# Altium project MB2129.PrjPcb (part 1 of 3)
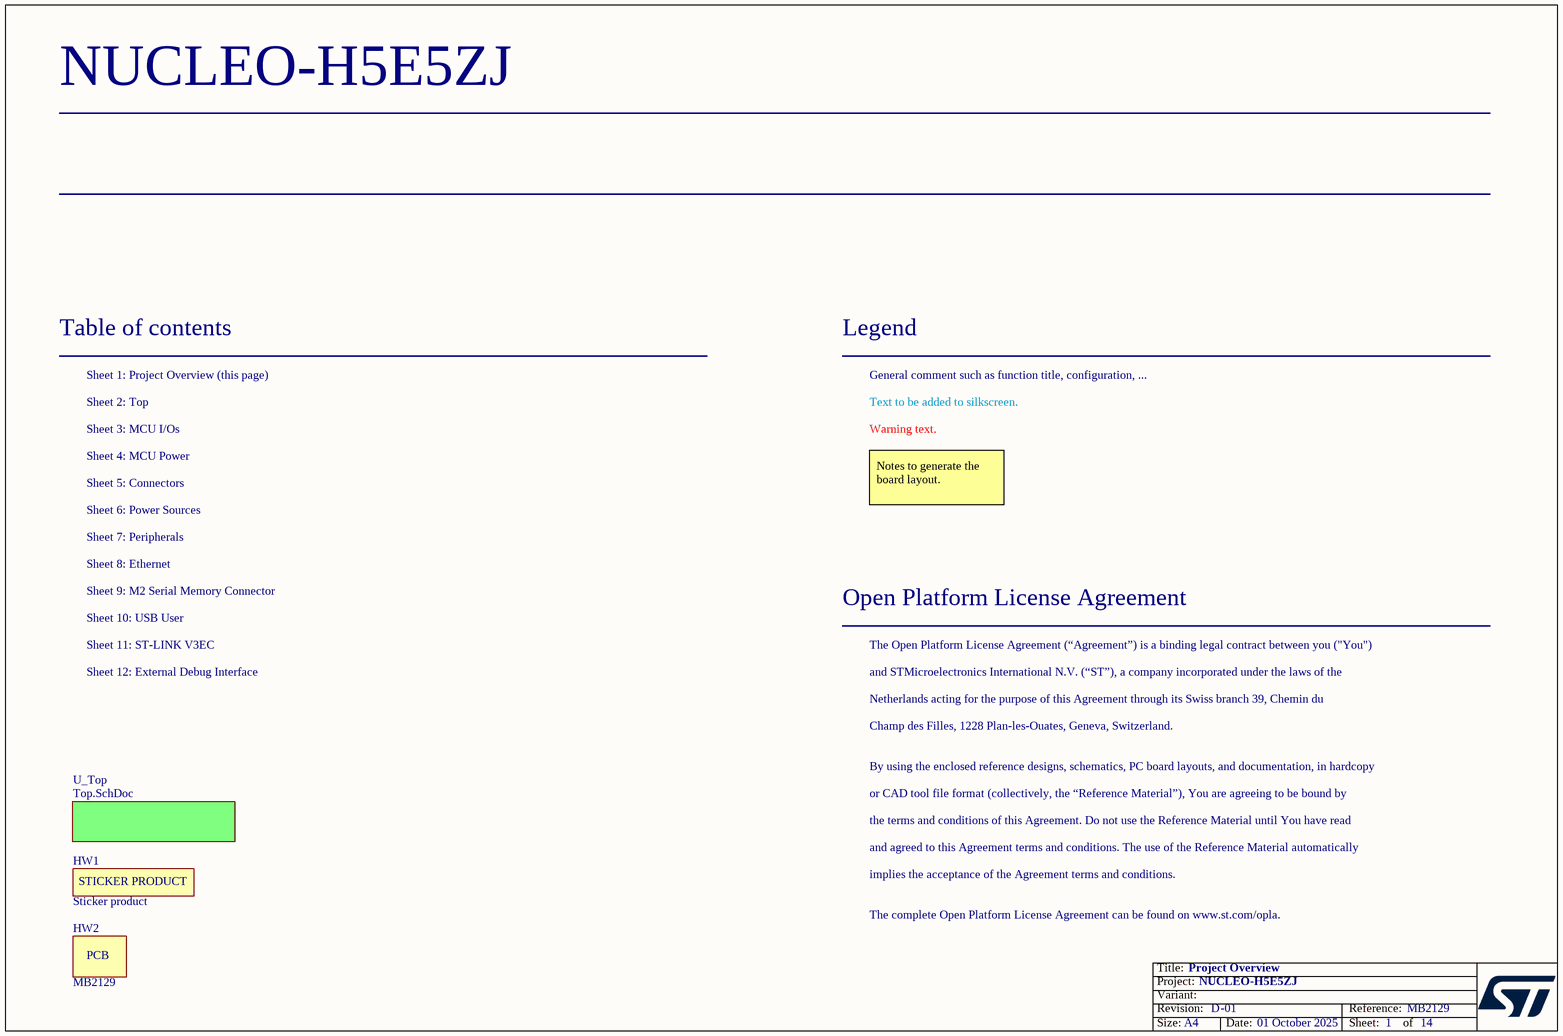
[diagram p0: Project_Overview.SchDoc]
Board_Assembly_Revision: 01; Board_Document_Date: 01 October 2025; Board_Name: NUCLEO-H5E5ZJ; Board_PCB_Revision: D; Board_Reference: MB2129
12 sheets, 381 parts. Net scope: flat (ports and power ports of the same name join across sheets).
Board file: MB2129.PcbDoc
Sheets:
  Project_Overview.SchDoc
    U_Top = Top.SchDoc
      U_Ethernet = Ethernet.SchDoc
      U_STLINK_V3EC = STLINK_V3EC.SchDoc
      U_External_Debug_Interface = External_Debug_Interface.SchDoc
      U_Connectors = Connectors.SchDoc
      U_MCU_Power = MCU_Power.SchDoc
      U_MCU_IOs = MCU_IOs.SchDoc
      U_Power_Sources = Power_Sources.SchDoc
      U_Peripherals = Peripherals.SchDoc
      U_M2_SerMem_Connector = M2_SerMem_Connector.SchDoc
      U_USB_User_UC2.1 = USB_User_UC2.1.SchDoc

## Sheet Project_Overview.SchDoc: Project Overview
size A4; Date: Not used; ApprovedBy: Not used; CheckedBy: Not used; Author: Not used; CompanyName: STMicroelectronics; DrawnBy: Not used; Engineer: Not used; Organization: Not used; Address1: Not used; Address2: Not used; Address3: Not used; Address4: Not used; DocumentNumber: 1; Revision: Not used; SheetNumber: 1; SheetTotal: 14

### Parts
HW1  value Sticker product  [STICKER_PRODUCT_25X9]  (hidden comment: STICKER_PRODUCT)  (no BOM)
HW2  value MB2129  (hidden comment: PCB)  (mechanical)

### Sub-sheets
U_Top = Top.SchDoc: no entries

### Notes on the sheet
- Table of contents
- Sheet 1: Project Overview (this page)
- Legend
- General comment such as function title, configuration, ...
- Sheet 2: Top
- Sheet 3: MCU I/Os
- Text to be added to silkscreen.
- Warning text.
- Sheet 4: MCU Power
- Sheet 5: Connectors
- Sheet 6: Power Sources
- Notes to generate the board layout.
- Sheet 8: Ethernet
- Sheet 7: Peripherals
- Sheet 10: USB User
- Sheet 11: ST-LINK V3EC
- Sheet 9: M2 Serial Memory Connector
- Open Platform License Agreement
- The Open Platform License Agreement (“Agreement”) is a binding legal contract between you ("You")
- Sheet 12: External Debug Interface
- and STMicroelectronics International N.V. (“ST”), a company incorporated under the laws of the
- Netherlands acting for the purpose of this Agreement through its Swiss branch 39, Chemin du
- Champ des Filles, 1228 Plan-les-Ouates, Geneva, Switzerland.
- By using the enclosed reference designs, schematics, PC board layouts, and documentation, in hardcopy
- or CAD tool file format (collectively, the “Reference Material”), You are agreeing to be bound by
- the terms and conditions of this Agreement. Do not use the Reference Material until You have read
- and agreed to this Agreement terms and conditions. The use of the Reference Material automatically
- implies the acceptance of the Agreement terms and conditions.
- The complete Open Platform License Agreement can be found on www.st.com/opla.

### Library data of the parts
HW1 = MCD-00547: Sticker product 25x9 mm; Part_Type: Misc; Part_Preference: Recommended; ShowFields: YES; ID: 3197
HW2 = MCD-04587: MB2129_RevB, 6L2S, STM32H5E5; Part_Preference: Recommended; Manufacturer: EISUN ELECTRONICS SHENZHEN CO; ShowFields: YES; ID: 6703

## Sheet Top.SchDoc: Top
size A4; Date: Not used; ApprovedBy: Not used; CheckedBy: Not used; Author: Not used; CompanyName: STMicroelectronics; DrawnBy: Not used; Engineer: Not used; Organization: Not used; Address1: Not used; Address2: Not used; Address3: Not used; Address4: Not used; DocumentNumber: 2; Revision: Not used; SheetNumber: 2; SheetTotal: 14
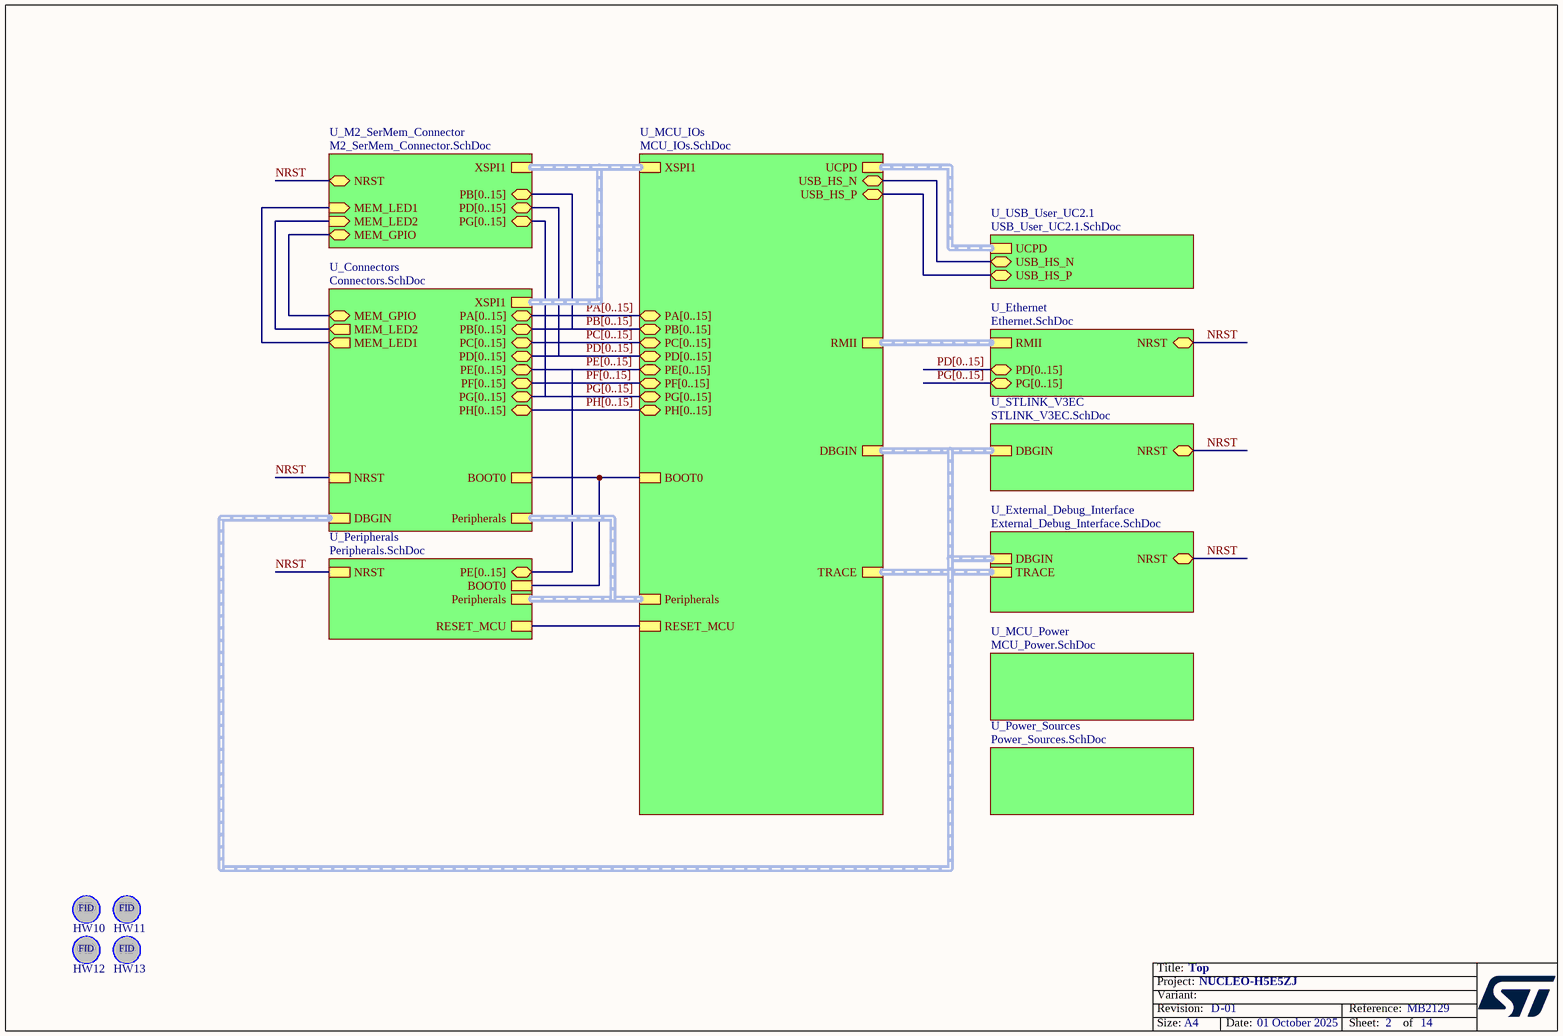
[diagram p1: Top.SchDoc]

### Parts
HW10  FiducialPad  [MIRE_PLACE_SMD_0P8MM]  (value not drawn)  (no BOM)
HW11  FiducialPad  [MIRE_PLACE_SMD_0P8MM]  (value not drawn)  (no BOM)
HW12  FiducialPad  [MIRE_PLACE_SMD_0P8MM]  (value not drawn)  (no BOM)
HW13  FiducialPad  [MIRE_PLACE_SMD_0P8MM]  (value not drawn)  (no BOM)

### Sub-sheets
U_Connectors = Connectors.SchDoc: PC[0..15] (bidir), PE[0..15] (bidir), PF[0..15] (bidir), PG[0..15] (bidir), PA[0..15] (bidir), PB[0..15] (bidir), BOOT0, PD[0..15] (bidir), NRST, Peripherals (harness Peripherals), MEM_LED1 (out), MEM_LED2 (out), MEM_GPIO (bidir), PH[0..15] (bidir), XSPI1 (harness XSPI1), DBGIN (harness DBGIN)
U_Ethernet = Ethernet.SchDoc: RMII (harness RMII), NRST (bidir), PD[0..15] (bidir), PG[0..15] (bidir)
U_External_Debug_Interface = External_Debug_Interface.SchDoc: TRACE (harness TRACE), NRST (bidir), DBGIN (harness DBGIN)
U_M2_SerMem_Connector = M2_SerMem_Connector.SchDoc: PB[0..15] (bidir), XSPI1 (harness XSPI1), NRST (bidir), MEM_LED1 (in), MEM_LED2 (in), MEM_GPIO (bidir), PD[0..15] (bidir), PG[0..15] (bidir)
U_MCU_IOs = MCU_IOs.SchDoc: Peripherals (harness Peripherals), TRACE (harness TRACE), RMII (harness RMII), PD[0..15] (bidir), PE[0..15] (bidir), PG[0..15] (bidir), PC[0..15] (bidir), PA[0..15] (bidir), PF[0..15] (bidir), PB[0..15] (bidir), BOOT0, UCPD (harness UCPD), USB_HS_N (bidir), USB_HS_P (bidir), DBGIN (harness DBGIN), XSPI1 (harness XSPI1), RESET_MCU, PH[0..15] (bidir)
U_MCU_Power = MCU_Power.SchDoc: no entries
U_Peripherals = Peripherals.SchDoc: Peripherals (harness Peripherals), NRST, BOOT0, RESET_MCU, PE[0..15] (bidir)
U_Power_Sources = Power_Sources.SchDoc: no entries
U_STLINK_V3EC = STLINK_V3EC.SchDoc: NRST (bidir), DBGIN (harness DBGIN)
U_USB_User_UC2.1 = USB_User_UC2.1.SchDoc: USB_HS_N (bidir), USB_HS_P (bidir), UCPD (harness UCPD)

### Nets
NRST: sheet U_Ethernet/NRST, sheet U_STLINK_V3EC/NRST, sheet U_External_Debug_Interface/NRST, sheet U_Connectors/NRST, sheet U_Peripherals/NRST, sheet U_M2_SerMem_Connector/NRST
(unnamed): sheet U_Connectors/BOOT0, sheet U_MCU_IOs/BOOT0, sheet U_Peripherals/BOOT0
(unnamed): sheet U_Connectors/MEM_LED1, sheet U_M2_SerMem_Connector/MEM_LED1  [a separate net that carries the same name]
(unnamed): sheet U_Connectors/MEM_LED2, sheet U_M2_SerMem_Connector/MEM_LED2  [a separate net that carries the same name]
(unnamed): sheet U_Connectors/MEM_GPIO, sheet U_M2_SerMem_Connector/MEM_GPIO  [a separate net that carries the same name]
(unnamed): sheet U_MCU_IOs/USB_HS_N, sheet U_USB_User_UC2.1/USB_HS_N  [a separate net that carries the same name]
(unnamed): sheet U_MCU_IOs/USB_HS_P, sheet U_USB_User_UC2.1/USB_HS_P  [a separate net that carries the same name]
(unnamed): sheet U_MCU_IOs/RESET_MCU, sheet U_Peripherals/RESET_MCU  [a separate net that carries the same name]

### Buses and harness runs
bus PA[0..15] = sheet U_Connectors/PA[0..15] = sheet U_MCU_IOs/PA[0..15]
bus PB[0..15] = sheet U_Connectors/PB[0..15] = sheet U_M2_SerMem_Connector/PB[0..15] = sheet U_MCU_IOs/PB[0..15]
bus PC[0..15] = sheet U_Connectors/PC[0..15] = sheet U_MCU_IOs/PC[0..15]
bus PD[0..15] = sheet U_Connectors/PD[0..15] = sheet U_M2_SerMem_Connector/PD[0..15] = sheet U_MCU_IOs/PD[0..15]
bus PD[0..15] = sheet U_Ethernet/PD[0..15]
bus PE[0..15] = sheet U_Connectors/PE[0..15] = sheet U_MCU_IOs/PE[0..15] = sheet U_Peripherals/PE[0..15]
bus PF[0..15] = sheet U_Connectors/PF[0..15] = sheet U_MCU_IOs/PF[0..15]
bus PG[0..15] = sheet U_Connectors/PG[0..15] = sheet U_M2_SerMem_Connector/PG[0..15] = sheet U_MCU_IOs/PG[0..15]
bus PG[0..15] = sheet U_Ethernet/PG[0..15]
bus PH[0..15] = sheet U_Connectors/PH[0..15] = sheet U_MCU_IOs/PH[0..15]
harness sheet U_Connectors/DBGIN = sheet U_External_Debug_Interface/DBGIN = sheet U_MCU_IOs/DBGIN = sheet U_STLINK_V3EC/DBGIN
harness sheet U_Connectors/Peripherals = sheet U_MCU_IOs/Peripherals = sheet U_Peripherals/Peripherals
harness sheet U_Connectors/XSPI1 = sheet U_M2_SerMem_Connector/XSPI1 = sheet U_MCU_IOs/XSPI1
harness sheet U_Ethernet/RMII = sheet U_MCU_IOs/RMII
harness sheet U_External_Debug_Interface/TRACE = sheet U_MCU_IOs/TRACE
harness sheet U_MCU_IOs/UCPD = sheet U_USB_User_UC2.1/UCPD

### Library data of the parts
HW10-HW13 = MCD-03135: Fiducial Pad, 0.8mm; Part_Type: Misc; Part_Preference: Recommended; ShowFields: YES; ID: 5251; Component_Country_Of_Origin: Unknown

## Sheet Ethernet.SchDoc: Ethernet
size A4; Date: Not used; ApprovedBy: Not used; CheckedBy: Not used; Author: Not used; CompanyName: STMicroelectronics; DrawnBy: Not used; Engineer: Not used; Organization: Not used; Address1: Not used; Address2: Not used; Address3: Not used; Address4: Not used; DocumentNumber: 8; Revision: Not used; SheetNumber: 8; SheetTotal: 14
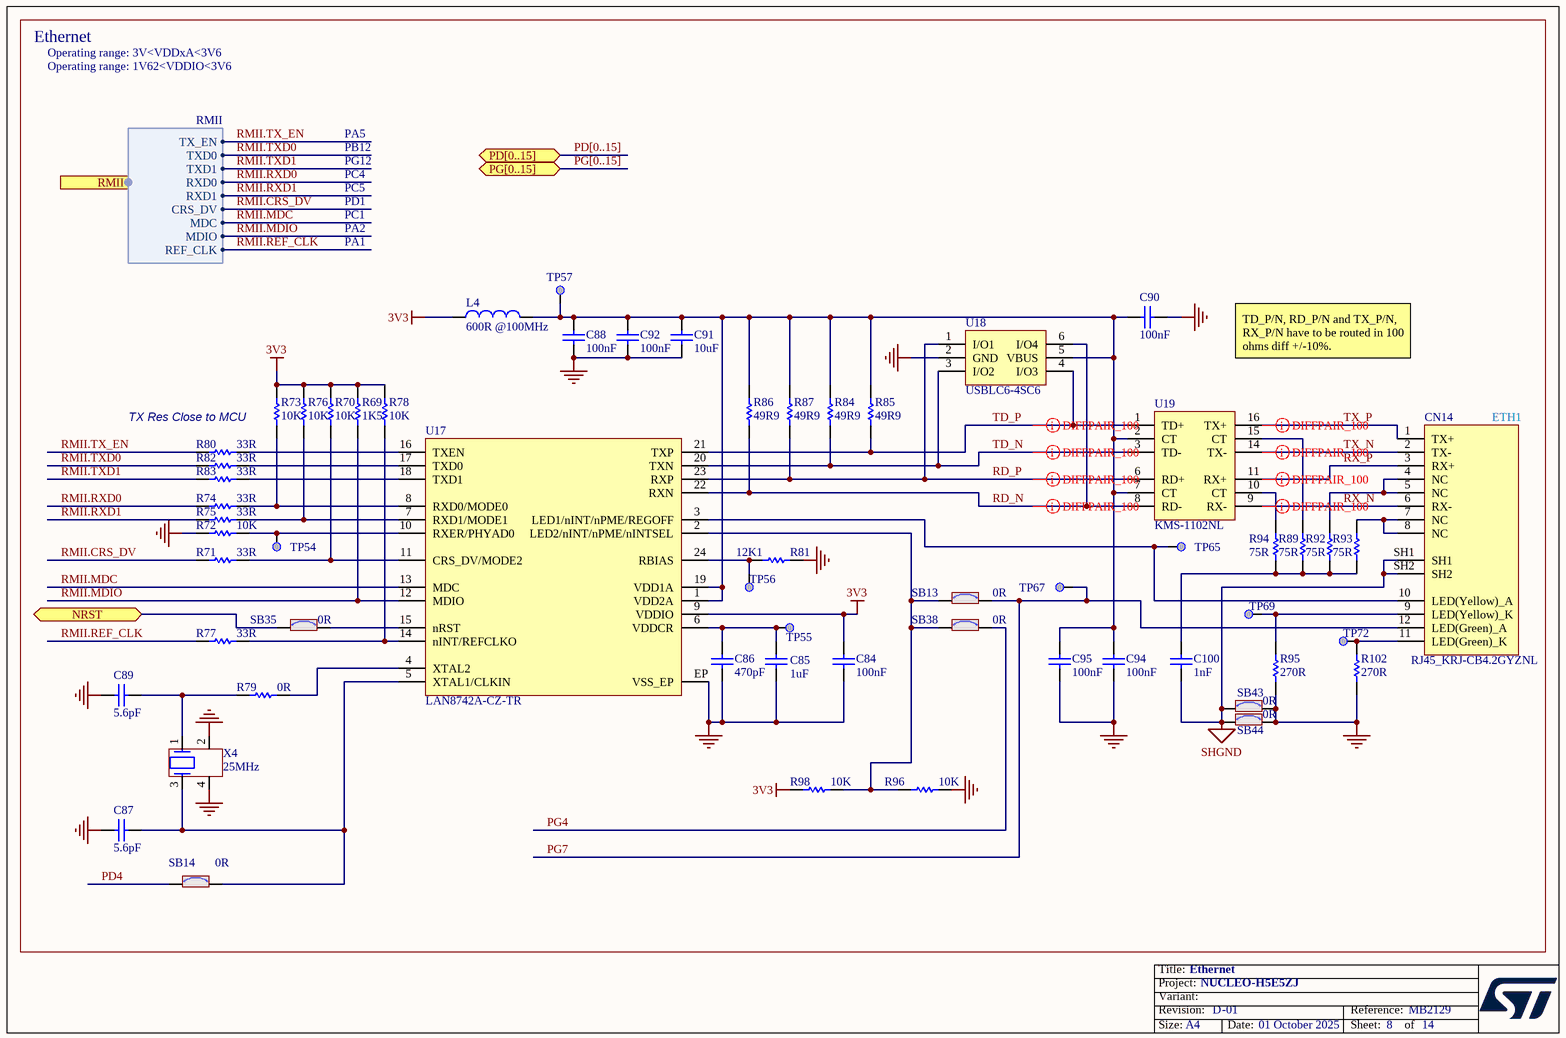
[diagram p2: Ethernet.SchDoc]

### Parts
C84  value 100nF  [C0402]  (hidden comment: Capacitor)
C85  value 1uF  [C0402]  (hidden comment: Capacitor)
C86  value 470pF  [C0402]  (hidden comment: Capacitor)
C87  value 5.6pF  [C0402]  (hidden comment: Capacitor)
C88  value 100nF  [C0402]  (hidden comment: Capacitor)
C89  value 5.6pF  [C0402]  (hidden comment: Capacitor)
C90  value 100nF  [C0402]  (hidden comment: Capacitor)
C91  value 10uF  [C0603]  (hidden comment: Capacitor)
C92  value 100nF  [C0402]  (hidden comment: Capacitor)
C94  value 100nF  [C0402]  (hidden comment: Capacitor)
C95  value 100nF  [C0402]  (hidden comment: Capacitor)
C100  value 1nF  [C1206_H1P6]  (hidden comment: Capacitor)
CN14  RJ45_KRJ-CB4.2GYZNL  [CON_RJ45_DGKYD_KRJ-CB4.2GYZNL]
L4  value 600R @100MHz  [L0603]  (hidden comment: BEAD)
R69  value 1K5  [R0402]  (hidden comment: Resistor)
R70  value 10K  [R0402]  (hidden comment: Resistor)
R71  value 33R  [R0402]  (hidden comment: Resistor)
R72  value 10K  [R0402]  (hidden comment: Resistor)
R73  value 10K  [R0402]  (hidden comment: Resistor)
R74  value 33R  [R0402]  (hidden comment: Resistor)
R75  value 33R  [R0402]  (hidden comment: Resistor)
R76  value 10K  [R0402]  (hidden comment: Resistor)
R77  value 33R  [R0402]  (hidden comment: Resistor)
R78  value 10K  [R0402]  (hidden comment: Resistor)
R79  value 0R  [R0402]  (hidden comment: Resistor)
R80  value 33R  [R0402]  (hidden comment: Resistor)
R81  value 12K1  [R0402]  (hidden comment: Resistor)
R82  value 33R  [R0402]  (hidden comment: Resistor)
R83  value 33R  [R0402]  (hidden comment: Resistor)
R84  value 49R9  [R0402]  (hidden comment: Resistor)
R85  value 49R9  [R0402]  (hidden comment: Resistor)
R86  value 49R9  [R0402]  (hidden comment: Resistor)
R87  value 49R9  [R0402]  (hidden comment: Resistor)
R89  value 75R  [R0402]  (hidden comment: Resistor)
R92  value 75R  [R0402]  (hidden comment: Resistor)
R93  value 75R  [R0402]  (hidden comment: Resistor)
R94  value 75R  [R0402]  (hidden comment: Resistor)
R95  value 270R  [R0402]  (hidden comment: Resistor)
R96  value 10K  [R0402]  (hidden comment: Resistor)
R98  value 10K  [R0402]  (hidden comment: Resistor)
R102  value 270R  [R0402]  (hidden comment: Resistor)
SB13  value 0R  [SOLDER-BRIDGE_R0603-0R]  (hidden comment: SB_ON)
SB14  value 0R  [SOLDER-BRIDGE_R0402-0R]  (hidden comment: SB_ON)
SB35  value 0R  [SOLDER-BRIDGE_R0603-0R]  (hidden comment: SB_ON)
SB38  value 0R  [SOLDER-BRIDGE_R0603-0R]  (hidden comment: SB_ON)
SB43  value 0R  [SOLDER-BRIDGE_R0603-0R]  (hidden comment: SB_ON)
SB44  value 0R  [SOLDER-BRIDGE_R0603-0R]  (hidden comment: SB_ON)
TP54  Test Point  [TP_SMD_0-6MM]  (value not drawn)  (no BOM)
TP55  Test Point  [TP_SMD_0-6MM]  (value not drawn)  (no BOM)
TP56  Test Point  [TP_SMD_0-6MM]  (value not drawn)  (no BOM)
TP57  Test Point  [TP_SMD_0-6MM]  (value not drawn)  (no BOM)
TP65  Test Point  [TP_SMD_0-6MM]  (value not drawn)  (no BOM)
TP67  Test Point  [TP_SMD_0-6MM]  (value not drawn)  (no BOM)
TP69  Test Point  [TP_SMD_0-6MM]  (value not drawn)  (no BOM)
TP72  Test Point  [TP_SMD_0-6MM]  (value not drawn)  (no BOM)
U17  LAN8742A-CZ-TR  [ICC_VQFN24-EPAD_4X4_P050]
U18  USBLC6-4SC6  [ESD_SOT23-6L]
U19  KMS-1102NL  [TRS_DGKYD_KMS-1102NL]
X4  value 25MHz  [CRY_NX2016SA_4P]  (hidden comment: XTAL_4_PINS)

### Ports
NRST (bidir), PD[0..15] (bidir), PG[0..15] (bidir), RMII (harness RMII)

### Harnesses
RMII: TX_EN, TXD0, TXD1, RXD0, RXD1, CRS_DV, MDC, MDIO, REF_CLK

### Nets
3V3: C84.2 L4.1 R69.2 R70.2 R73.2 R76.2 R78.2 R98.2 U17.9(VDDIO)
GND: C84.1 C85.1 C86.1 C87.1 C88.1 C89.1 C90.1 C91.1 C92.1 C94.1 C95.1 R72.2 R81.2 R95.1 R96.1 R102.1 SB43.2 SB44.2 U17.EP(VSS_EP) U18.2(GND) X4.2 X4.4
SHGND: C100.1 CN14.SH1 CN14.SH2 SB43.1 SB44.1
NRST: SB35.1 ; port NRST
PD4: SB14.1
PG4: SB38.2
PG7: CN14.12(LED(Green)_A) SB13.2 TP67.1
RD_N: R86.1 U17.22(RXN) U18.6(I/O4) U19.8(RD-)
RD_P: R87.1 U17.23(RXP) U18.1(I/O1) U19.6(RD+)
RMII.CRS_DV: R71.1 ; port RMII.CRS_DV
RMII.MDC: U17.13(MDC) ; port RMII.MDC
RMII.MDIO: R69.1 U17.12(MDIO) ; port RMII.MDIO
RMII.REF_CLK: R77.1 ; port RMII.REF_CLK
RMII.RXD0: R74.1 ; port RMII.RXD0
RMII.RXD1: R75.1 ; port RMII.RXD1
RMII.TX_EN: R80.1 ; port RMII.TX_EN
RMII.TXD0: R82.1 ; port RMII.TXD0
RMII.TXD1: R83.1 ; port RMII.TXD1
RX_N: CN14.6(RX-) U19.9(RX-)
RX_P: CN14.3(RX+) U19.11(RX+)
TD_N: R84.1 U17.20(TXN) U18.3(I/O2) U19.3(TD-)
TD_P: R85.1 U17.21(TXP) U18.4(I/O3) U19.1(TD+)
TX_N: CN14.2(TX-) U19.14(TX-)
TX_P: CN14.1(TX+) U19.16(TX+)
NetC85_2: C85.2 C86.2 TP55.1 U17.6(VDDCR)
NetC87_2: C87.2 SB14.2 U17.5(XTAL1/CLKIN) X4.3
NetC88_2: C88.2 C90.2 C91.2 C92.2 C94.2 C95.2 L4.2 R84.2 R85.2 R86.2 R87.2 TP57.1 U17.1(VDD2A) U17.19(VDD1A) U18.5(VBUS) U19.2(CT) U19.7(CT)
NetC89_2: C89.2 R79.1 X4.1
NetC100_2: C100.2 R89.1 R92.1 R93.1 R94.1
NetCN14_4: CN14.4(NC) CN14.5(NC) R92.2
NetCN14_7: CN14.7(NC) CN14.8(NC) R93.2
NetCN14_9: CN14.9(LED(Yellow)_K) R95.2 TP69.1
NetCN14_10: CN14.10(LED(Yellow)_A) TP65.1 U17.3(LED1/nINT/nPME/REGOFF)
NetCN14_11: CN14.11(LED(Green)_K) R102.2 TP72.1
NetR70_1: R70.1 R71.2 U17.11(CRS_DV/MODE2)
NetR72_1: R72.1 TP54.1 U17.10(RXER/PHYAD0)
NetR73_1: R73.1 R74.2 U17.8(RXD0/MODE0)
NetR75_2: R75.2 R76.1 U17.7(RXD1/MODE1)
NetR77_2: R77.2 R78.1 U17.14(nINT/REFCLKO)
NetR79_2: R79.2 U17.4(XTAL2)
NetR80_2: R80.2 U17.16(TXEN)
NetR81_1: R81.1 TP56.1 U17.24(RBIAS)
NetR82_2: R82.2 U17.17(TXD0)
NetR83_2: R83.2 U17.18(TXD1)
NetR89_2: R89.2 U19.15(CT)
NetR94_2: R94.2 U19.10(CT)
NetR96_2: R96.2 R98.1 SB13.1 SB38.1 U17.2(LED2/nINT/nPME/nINTSEL)
NetSB35_2: SB35.2 U17.15(nRST)

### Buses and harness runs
bus PD[0..15] = port PD[0..15]
bus PG[0..15] = port PG[0..15]

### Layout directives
differential pair; differential pair class DiffPair_100; net class 100 ohms diff: RD_N, RD_P, RX_N, RX_P, TD_N, TD_P, TX_N, TX_P

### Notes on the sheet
- Operating range: 3V<VDDxA<3V6
- Operating range: 1V62<VDDIO<3V6
- PA5
- PB12
- PG12
- PC4
- PC5
- PD1
- PC1
- PA2
- PA1
- TD_P/N, RD_P/N and TX_P/N, RX_P/N have to be routed in 100 ohms diff +/-10%.
- TX Res Close to MCU
- (near CN14) ETH1

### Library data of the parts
C84 C88 C90 C92 C94 C95 = MCD-00006: Capacitor, MLCC, 100nF, 16V, X7R, +/-10%, 0402, T=0.5mm; Part_Preference: Recommended; Manufacturer: YAGEO; Manufacturer_Part_Number: CC0402KRX7R7BB104; Partial_Alternate_Internal_Part_Number: MCD-03299; Order_Code_RS: 9402047; Component_Country_Of_Origin: China; ShowFields: YES; ID: 2474
C85 = MCD-01722: Capacitor, MLCC, 1uF, 10V, X5R, +/-10%, 0402, T=0.5mm; Part_Preference: Recommended; Manufacturer: YAGEO; Manufacturer_Part_Number: CC0402KRX5R6BB105; Component_Country_Of_Origin: China; ShowFields: YES; ID: 3822
C86 = MCD-00724: Capacitor, MLCC, 470pF, 50V, NPO, +/-5%, 0402, T=0.5mm; Manufacturer_Part_Number: CC0402JRNPO9BN471; Manufacturer: YAGEO; Part_Preference: Recommended; Order_Code_RS: 199-2186; Component_Country_Of_Origin: China; ShowFields: YES; ID: 3023
C87 C89 = MCD-01374: Capacitor, MLCC, 5.6pF, 50V, NPO, +/-0.1pF, 0402, T=0.5mm; Manufacturer_Part_Number: CC0402BRNPO9BN5R6; Manufacturer: YAGEO; Part_Preference: Recommended; Component_Country_Of_Origin: China; ShowFields: YES; ID: 3474
C91 = MCD-00099: Capacitor, MLCC, 10uF, 10V, X5R, +/-10%, 0603, T=0.8mm; Part_Preference: Recommended; Manufacturer: MURATA; Manufacturer_Part_Number: GRM188R61A106KE69D; Partial_Alternate_Internal_Part_Number: MCD-03152; Order_Code_RS: 2494233; Component_Country_Of_Origin: Japan°°; ShowFields: YES; ID: 2770
C100 = MCD-00722: Capacitor, MLCC, 1nF, 2KV, X7R, +/-10%, 1206, T=1.25mm; Manufacturer_Part_Number: CC1206KKX7RDBB102; Manufacturer: YAGEO; Part_Preference: Recommended; Component_Country_Of_Origin: China; ShowFields: YES; ID: 3027
CN14 = MCD-00717: Connector_RJ45, single port, with LEDS, T= 11.05mm; Manufacturer: DONGGUAN KEYOUDA ELECTRONIC TECHNOLOGY; Part_Preference: Recommended; Component_Country_Of_Origin: Unknown; ShowFields: YES; ID: 3029
L4 = MCD-02437: Ferrite bead, 600R@100MHz, +/-25%, 500mA, 380mR, 0603, T=0.8mm; Part_Type: Inductor; Part_Preference: Recommended; Manufacturer: MURATA; Manufacturer_Part_Number: BLM18AG601SN1D; Order_Code_RS: 724-1299; Component_Country_Of_Origin: Japan°; ShowFields: YES; ID: 4543
R69 = MCD-00068: Resistor, 1K5, 0402, +/-1%, 1/16W; Manufacturer_Part_Number: RC0402FR-071K5L; Manufacturer: YAGEO; Part_Preference: Recommended; Order_Code_RS: 9239251; Component_Country_Of_Origin: China; ShowFields: YES; ID: 2524
R70 R72 R73 R76 R78 R96 R98 = MCD-00053: Resistor, 10K, 0402, +/-1%, 1/16W; Manufacturer_Part_Number: RC0402FR-0710KL; Manufacturer: YAGEO; BMS_Part_Number: 9131590; Part_Preference: Recommended; Order_Code_RS: 9239359; Component_Country_Of_Origin: China; ShowFields: YES; ID: 2539
R71 R74 R75 R77 R80 R82 R83 = MCD-00455: Resistor, 33R, 0402, +/-1%, 1/16W; Manufacturer_Part_Number: RC0402FR-0733RL; Manufacturer: YAGEO; Part_Preference: Recommended; Component_Country_Of_Origin: China; ShowFields: YES; ID: 2821
R79 = MCD-00052: Resistor, 0R, 0402, +/-5%, 1/16W; Manufacturer_Part_Number: RC0402JR-070RL; Manufacturer: YAGEO; Part_Preference: Recommended; Order_Code_RS: 9232516RL; Component_Country_Of_Origin: China; ShowFields: YES; ID: 2540
R81 = MCD-00723: Resistor, 12K1, 0402, +/-1%, 1/16W; Manufacturer_Part_Number: RC0402FR-0712K1L; Manufacturer: YAGEO; Part_Preference: Recommended; Component_Country_Of_Origin: China; ShowFields: YES; ID: 3022
R84-R87 = MCD-00565: Resistor, 49R9, 0402, +/-1%, 1/16W; Manufacturer_Part_Number: RC0402FR-0749R9L; Manufacturer: YAGEO; Part_Preference: Recommended; Component_Country_Of_Origin: China; ShowFields: YES; ID: 3178
R89 R92-R94 = MCD-00515: Resistor, 75R, 0402, +/-1%, 1/16W; Manufacturer_Part_Number: RC0402FR-0775RL; Manufacturer: YAGEO; Part_Preference: Recommended; Component_Country_Of_Origin: China; ShowFields: YES; ID: 3229
R95 R102 = MCD-00441: Resistor, 270R, 0402, +/-1%, 1/16W; Manufacturer_Part_Number: RC0402FR-07270RL; Manufacturer: YAGEO; Part_Preference: Recommended; Component_Country_Of_Origin: China; ShowFields: YES; ID: 2838
SB13 SB35 SB38 SB43 SB44 = MCD-00071: Resistor, 0R, SB0603, 5%, 0.1W; Manufacturer_Part_Number: RC0603JR-070RL; Manufacturer: YAGEO; Part_Preference: Recommended; Manufacturer_HQ_COO: Unknown; Order_Code_RS: 199-5647; Component_Country_Of_Origin: China; ShowFields: YES; ID: 2521
SB14 = MCD-01618: Resistor, 0R, SB0402, 5%, 0.063W; Manufacturer_Part_Number: RC0402JR-070RL; Manufacturer: YAGEO; Part_Preference: Recommended; Order_Code_RS: 618-5804; Component_Country_Of_Origin: China; ID: 3718; ShowFields: YES
TP54-TP57 TP65 TP67 TP69 TP72 = MCD-00631: Test Point 0.6mm; Part_Type: Misc; Part_Preference: Recommended; ShowFields: YES; ID: 3108; Component_Country_Of_Origin: Unknown
U17 = MCD-00719: ETHERNET Transceiver, Small Footprint RMII, 10/100M, with HP Auto-MDIX and flexPWR technology; BMS_Part_Number: 9177984; Part_Type: IC; Part_Preference: Recommended; Manufacturer: MICROCHIP; Partial_Alternate_Internal_Part_Number: MCD-03200; Order_Code_RS: 215-3925; Component_Country_Of_Origin: Unknown; ShowFields: YES; ID: 3026
U18 = MCD-00250: Very low capacitance ESD protection , 4 lines; Part_Type: IC; Manufacturer: STMICROELECTRONICS; BMS_Part_Number: 9151001; Part_Preference: Recommended; Manufacturer_HQ_COO: EU; Component_Country_Of_Origin: China; ShowFields: YES; ID: 2616
U19 = MCD-00718: Discrete magnetic transformer module, 16 pins, SMT, 100 Base-TX; Part_Type: IC; Manufacturer: DONGGUAN KEYOUDA ELECTRONIC TECHNOLOGY; Part_Preference: Recommended; Component_Country_Of_Origin: Unknown; ShowFields: YES; ID: 3030
X4 = MCD-01364: Crystal, 25MHz, 6pF, +/-20ppm, 80R, 2x1.6mm; Part_Type: Crystal_Osc; Manufacturer_Part_Number: NX2016SA-25MHZ-EXS00A-CS11321; Manufacturer: NDK; BMS_Part_Number: 9157044; Part_Preference: Recommended; Component_Country_Of_Origin: Unknown; ShowFields: YES; ID: 3464

## Sheet STLINK_V3EC.SchDoc: STLINK-V3EC
size A3; Date: Not used; ApprovedBy: Not used; CheckedBy: Not used; Author: Not used; CompanyName: STMicroelectronics; DrawnBy: Not used; Engineer: Not used; Organization: Not used; Address1: Not used; Address2: Not used; Address3: Not used; Address4: Not used; DocumentNumber: 12; Revision: Not used; SheetNumber: 12; SheetTotal: 14
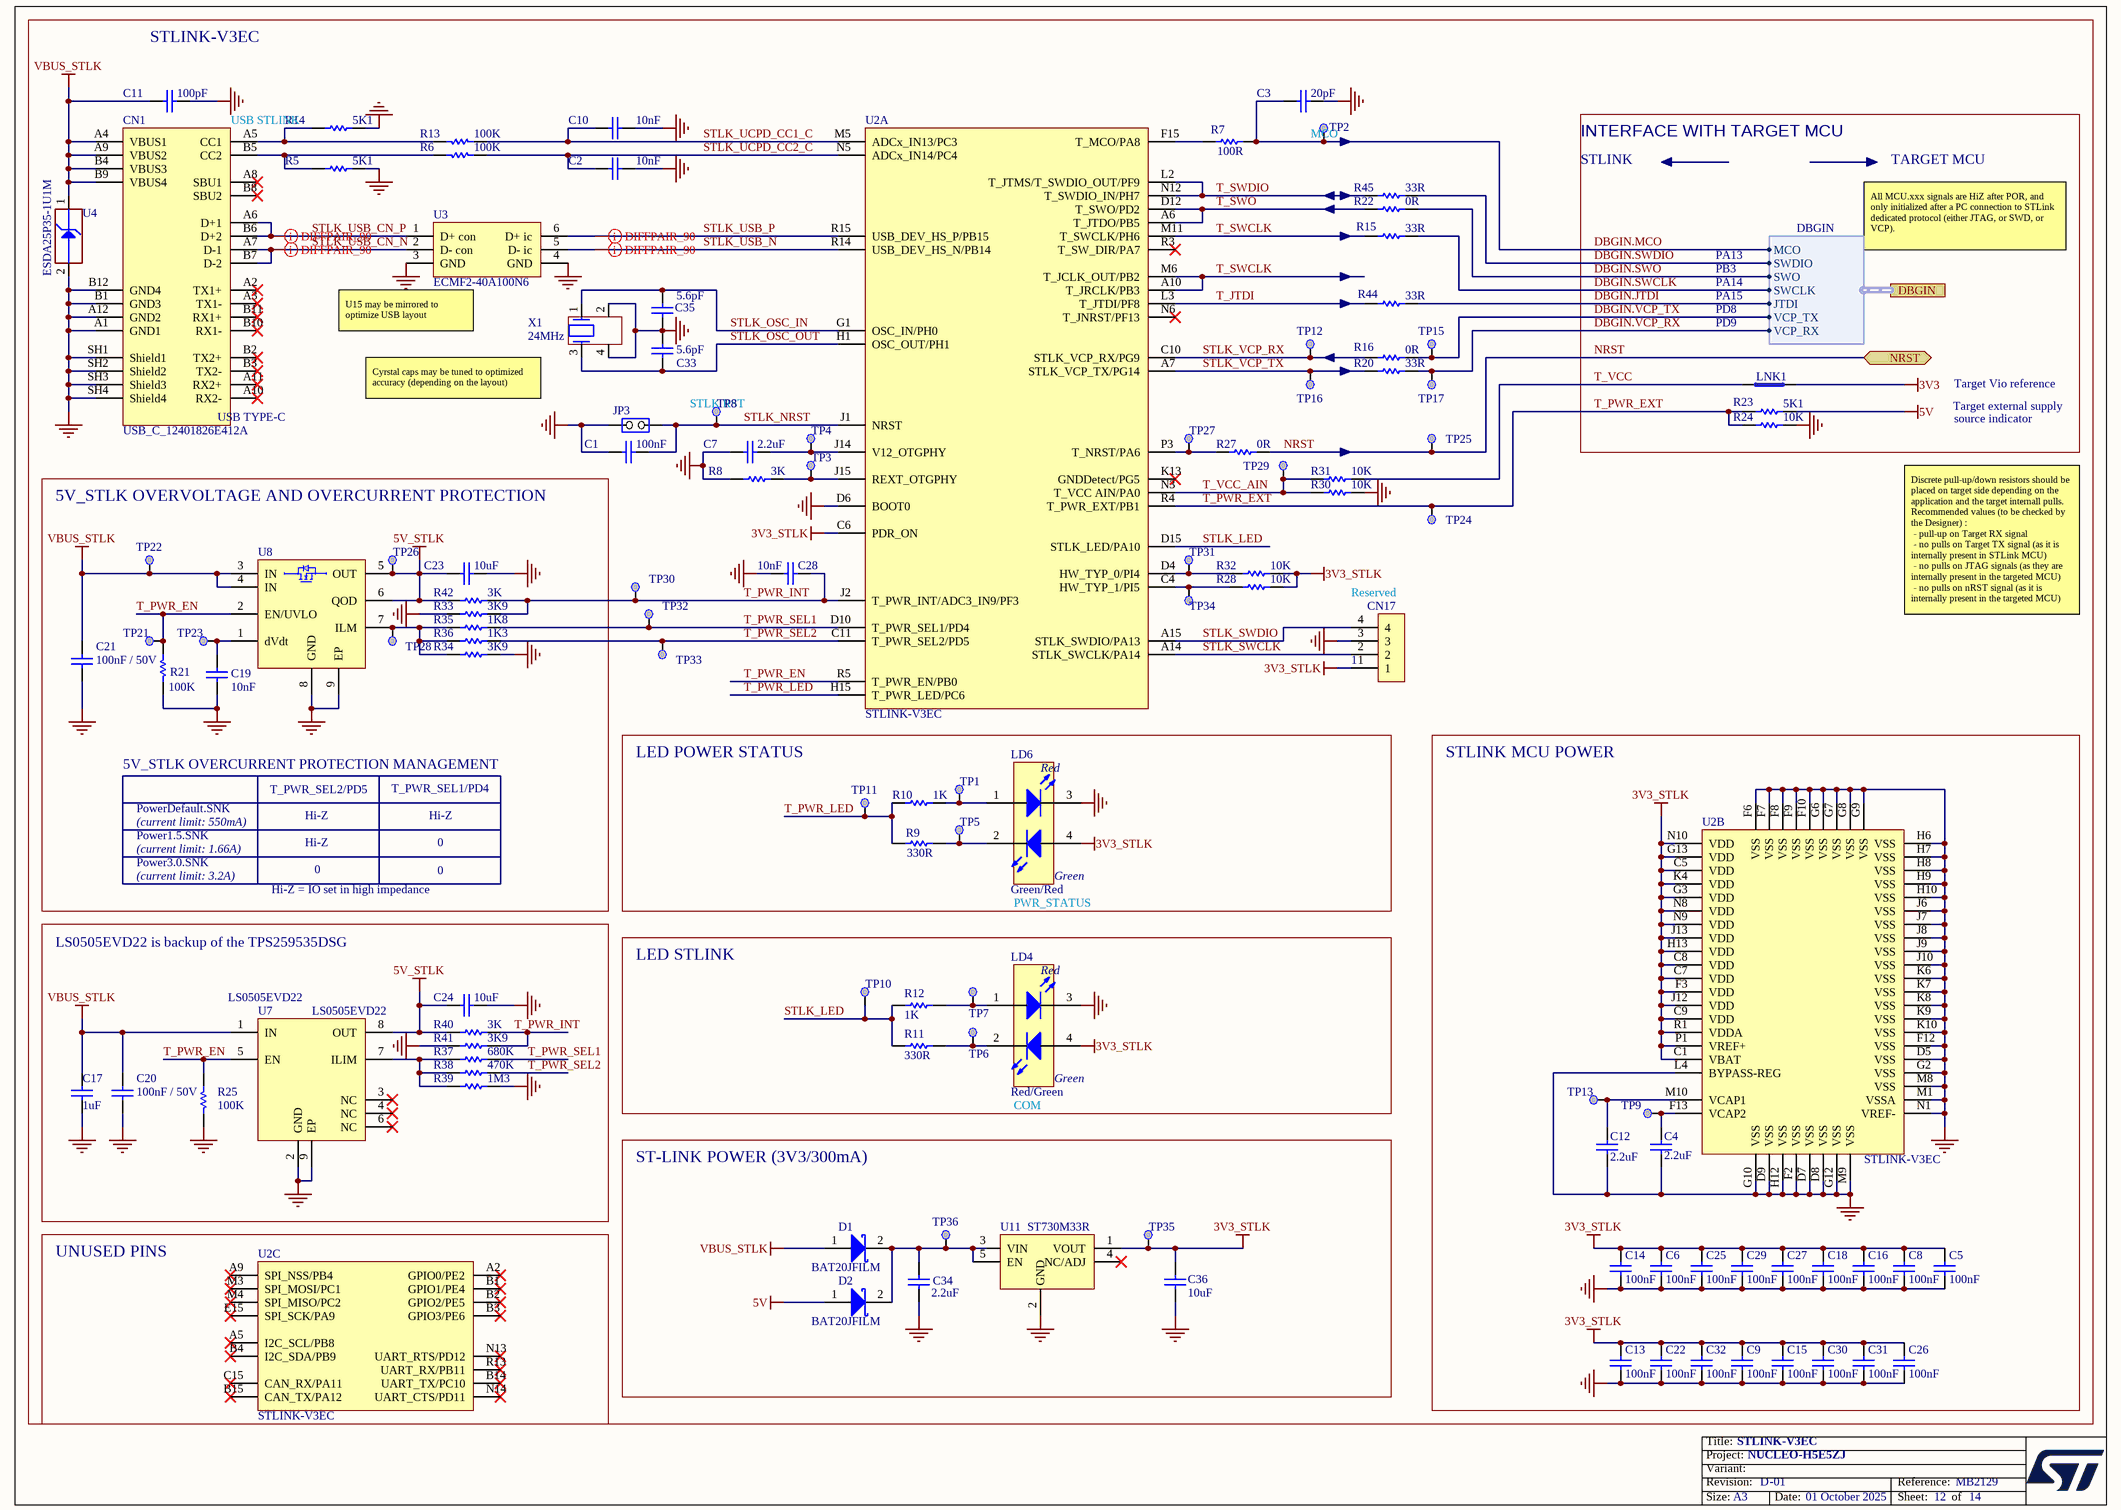
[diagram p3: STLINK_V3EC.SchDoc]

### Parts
C1  value 100nF  [C0402]  (hidden comment: Capacitor)
C2  value 10nF  [C0402]  (hidden comment: Capacitor)
C3  value 20pF  [C0402]  (hidden comment: Capacitor)
C4  value 2.2uF  [C0402]  (hidden comment: Capacitor)
C5  value 100nF  [C0402]  (hidden comment: Capacitor)
C6  value 100nF  [C0402]  (hidden comment: Capacitor)
C7  value 2.2uF  [C0402]  (hidden comment: Capacitor)
C8  value 100nF  [C0402]  (hidden comment: Capacitor)
C9  value 100nF  [C0402]  (hidden comment: Capacitor)
C10  value 10nF  [C0402]  (hidden comment: Capacitor)
C11  value 100pF  [C0402]  (hidden comment: Capacitor)
C12  value 2.2uF  [C0402]  (hidden comment: Capacitor)
C13  value 100nF  [C0402]  (hidden comment: Capacitor)
C14  value 100nF  [C0402]  (hidden comment: Capacitor)
C15  value 100nF  [C0402]  (hidden comment: Capacitor)
C16  value 100nF  [C0402]  (hidden comment: Capacitor)
C17  value 1uF  [C0402]  (hidden comment: Capacitor)
C18  value 100nF  [C0402]  (hidden comment: Capacitor)
C19  value 10nF  [C0402]  (hidden comment: Capacitor)
C20  value 100nF / 50V  [C0603]  (hidden comment: Capacitor)
C21  value 100nF / 50V  [C0603]  (hidden comment: Capacitor)
C22  value 100nF  [C0402]  (hidden comment: Capacitor)
C23  value 10uF  [C0603]  (hidden comment: Capacitor)
C24  value 10uF  [C0603]  (hidden comment: Capacitor)
C25  value 100nF  [C0402]  (hidden comment: Capacitor)
C26  value 100nF  [C0402]  (hidden comment: Capacitor)
C27  value 100nF  [C0402]  (hidden comment: Capacitor)
C28  value 10nF  [C0402]  (hidden comment: Capacitor)
C29  value 100nF  [C0402]  (hidden comment: Capacitor)
C30  value 100nF  [C0402]  (hidden comment: Capacitor)
C31  value 100nF  [C0402]  (hidden comment: Capacitor)
C32  value 100nF  [C0402]  (hidden comment: Capacitor)
C33  value 5.6pF  [C0402]  (hidden comment: Capacitor)
C34  value 2.2uF  [C0805]  (hidden comment: Capacitor)
C35  value 5.6pF  [C0402]  (hidden comment: Capacitor)
C36  value 10uF  [C0603]  (hidden comment: Capacitor)
CN1  value USB_C_12401826E412A  [CON_USB-TYPEC_AMPHENOL_12401826E412A]  (hidden comment: USB_TYPE_C_Receptacle)
CN17  Header 4x1  [CON_SAMTEC_TSW-104-07-G-S]  (value not drawn)
D1  value BAT20JFILM  [DIO_SOD323_1A_2K]  (hidden comment: SCHOTTKY_1A_2K)
D2  value BAT20JFILM  [DIO_SOD323_1A_2K]  (hidden comment: SCHOTTKY_1A_2K)
JP3  Jumper_Header 2x1  [CON_SAMTEC_TSW-102-07-G-S]  (value not drawn)
LD4  value Red/Green  [LED_BI-GR_WE-150141SV73110]  (hidden comment: LED_BICOLOR)
LD6  value Green/Red  [LED_BI-GR_WE-150141SV73110]  (hidden comment: LED_BICOLOR)
LNK1  link_200  [LINK200]  (value not drawn)  (no BOM)
R5  value 5K1  [R0402]  (hidden comment: Resistor)
R6  value 100K  [R0402]  (hidden comment: Resistor)
R7  value 100R  [R0402]  (hidden comment: Resistor)
R8  value 3K  [R0402]  (hidden comment: Resistor)
R9  value 330R  [R0402]  (hidden comment: Resistor)
R10  value 1K  [R0402]  (hidden comment: Resistor)
R11  value 330R  [R0402]  (hidden comment: Resistor)
R12  value 1K  [R0402]  (hidden comment: Resistor)
R13  value 100K  [R0402]  (hidden comment: Resistor)
R14  value 5K1  [R0402]  (hidden comment: Resistor)
R15  value 33R  [R0402]  (hidden comment: Resistor)
R16  value 0R  [R0402]  (hidden comment: Resistor)
R20  value 33R  [R0402]  (hidden comment: Resistor)
R21  value 100K  [R0402]  (hidden comment: Resistor)
R22  value 0R  [R0402]  (hidden comment: Resistor)
R23  value 5K1  [R0402]  (hidden comment: Resistor)
R24  value 10K  [R0402]  (hidden comment: Resistor)
R25  value 100K  [R0402]  (hidden comment: Resistor)
R27  value 0R  [R0402]  (hidden comment: Resistor)
R28  value 10K  [R0402]  (hidden comment: Resistor)
R30  value 10K  [R0402]  (hidden comment: Resistor)
R31  value 10K  [R0402]  (hidden comment: Resistor)
R32  value 10K  [R0402]  (hidden comment: Resistor)
R33  value 3K9  [R0402]  (hidden comment: Resistor)
R34  value 3K9  [R0402]  (hidden comment: Resistor)
R35  value 1K8  [R0402]  (hidden comment: Resistor)
R36  value 1K3  [R0402]  (hidden comment: Resistor)
R37  value 680K  [R0402]  (hidden comment: Resistor)
R38  value 470K  [R0402]  (hidden comment: Resistor)
R39  value 1M3  [R0402]  (hidden comment: Resistor)
R40  value 3K  [R0402]  (hidden comment: Resistor)
R41  value 3K9  [R0402]  (hidden comment: Resistor)
R42  value 3K  [R0402]  (hidden comment: Resistor)
R44  value 33R  [R0402]  (hidden comment: Resistor)
R45  value 33R  [R0402]  (hidden comment: Resistor)
TP1  Test Point  [TP_SMD_0-6MM]  (value not drawn)  (no BOM)
TP2  Test Point  [TP_SMD_1MM]  (value not drawn)  (no BOM)
TP3  Test Point  [TP_SMD_0-6MM]  (value not drawn)  (no BOM)
TP4  Test Point  [TP_SMD_0-6MM]  (value not drawn)  (no BOM)
TP5  Test Point  [TP_SMD_0-6MM]  (value not drawn)  (no BOM)
TP6  Test Point  [TP_SMD_0-6MM]  (value not drawn)  (no BOM)
TP7  Test Point  [TP_SMD_0-6MM]  (value not drawn)  (no BOM)
TP8  Test Point  [TP_SMD_0-6MM]  (value not drawn)  (no BOM)
TP9  Test Point  [TP_SMD_0-6MM]  (value not drawn)  (no BOM)
TP10  Test Point  [TP_SMD_0-6MM]  (value not drawn)  (no BOM)
TP11  Test Point  [TP_SMD_0-6MM]  (value not drawn)  (no BOM)
TP12  Test Point  [TP_SMD_0-6MM]  (value not drawn)  (no BOM)
TP13  Test Point  [TP_SMD_0-6MM]  (value not drawn)  (no BOM)
TP15  Test Point  [TP_SMD_0-6MM]  (value not drawn)  (no BOM)
TP16  Test Point  [TP_SMD_0-6MM]  (value not drawn)  (no BOM)
TP17  Test Point  [TP_SMD_0-6MM]  (value not drawn)  (no BOM)
TP21  Test Point  [TP_SMD_0-6MM]  (value not drawn)  (no BOM)
TP22  Test Point  [TP_SMD_0-6MM]  (value not drawn)  (no BOM)
TP23  Test Point  [TP_SMD_0-6MM]  (value not drawn)  (no BOM)
TP24  Test Point  [TP_SMD_0-6MM]  (value not drawn)  (no BOM)
TP25  Test Point  [TP_SMD_0-6MM]  (value not drawn)  (no BOM)
TP26  Test Point  [TP_SMD_0-6MM]  (value not drawn)  (no BOM)
TP27  Test Point  [TP_SMD_0-6MM]  (value not drawn)  (no BOM)
TP28  Test Point  [TP_SMD_0-6MM]  (value not drawn)  (no BOM)
TP29  Test Point  [TP_SMD_0-6MM]  (value not drawn)  (no BOM)
TP30  Test Point  [TP_SMD_0-6MM]  (value not drawn)  (no BOM)
TP31  Test Point  [TP_SMD_0-6MM]  (value not drawn)  (no BOM)
TP32  Test Point  [TP_SMD_0-6MM]  (value not drawn)  (no BOM)
TP33  Test Point  [TP_SMD_0-6MM]  (value not drawn)  (no BOM)
TP34  Test Point  [TP_SMD_0-6MM]  (value not drawn)  (no BOM)
TP35  Test Point  [TP_SMD_0-6MM]  (value not drawn)  (no BOM)
TP36  Test Point  [TP_SMD_0-6MM]  (value not drawn)  (no BOM)
U2  STLINK-V3EC  [ICC_UFBGA201_176+25_10X10_P065]  (parts A,B,C of 3)
U3  ECMF2-40A100N6  [ESD_UQFN-6L_1P45X1P4_P040]
U4  value ESDA25P35-1U1M  [ESD_QFN1610_2N_1K_2A]  (hidden comment: ESD-TRANSIL)
U7  LS0505EVD22  [ICC_DFN8-EPAD_2X2_P050_H0P8]
U8  TPS259535DSG  [ICC_WSON8-EPAD_2X2_P050]  (value not drawn)
U11  ST730M33R  [ICC_SOT23-5L_H1P45]
X1  value 24MHz  [CRY_NX2016SA_4P]  (hidden comment: XTAL_4_PINS)

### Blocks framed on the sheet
INTERFACE WITH TARGET MCU: LNK1 R23 R24
5V_STLK OVERVOLTAGE AND OVERCURRENT PROTECTION: C19 C21 C23 R21 R33-R36 R42 TP21-TP23 TP26 TP28 U8
LED POWER STATUS: LD6 R9 R10 TP1 TP5 TP11
STLINK MCU POWER: C4-C6 C8 C9 C12-C16 C18 C22 C25-C27 C29-C32 TP9 TP13 U2
LS0505EVD22 is backup of the TPS259535DSG: C17 C20 C24 R25 R37-R41 U7
LED STLINK: LD4 R11 R12 TP6 TP7 TP10
ST-LINK POWER (3V3/300mA): C34 C36 D1 D2 TP35 TP36 U11
UNUSED PINS: U2

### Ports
DBGIN (harness DBGIN), NRST (bidir)

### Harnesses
DBGIN: SWDIO, SWO, VCP_TX, SWCLK, VCP_RX, MCO, JTDI

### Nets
3V3: LNK1.1
3V3_STLK: C5.1 C6.1 C8.1 C9.1 C13.1 C14.1 C15.1 C16.1 C18.1 C22.1 C25.1 C26.1 C27.1 C29.1 C30.1 C31.1 C32.1 C36.2 CN17.1 LD4.4(Green_anode) LD6.4(Green_anode) R28.2 R32.2 TP35.1 U2.C1(VBAT) U2.C5(VDD) U2.C6(PDR_ON) U2.C7(VDD) U2.C8(VDD) U2.C9(VDD) U2.F3(VDD) U2.G3(VDD) U2.G13(VDD) U2.H13(VDD) U2.J12(VDD) U2.J13(VDD) U2.K4(VDD) U2.N8(VDD) U2.N9(VDD) U2.N10(VDD) U2.P1(VREF+) U2.R1(VDDA) U11.1(VOUT)
5V: D2.1(A) R23.2
5V_STLK: C23.2 C24.2 R40.1 R42.1 TP26.1 U7.8(OUT) U8.5(OUT) U8.6(QOD)
GND: C1.1 C2.2 C3.1 C4.1 C5.2 C6.2 C7.1 C8.2 C9.2 C10.2 C11.2 C12.1 C13.2 C14.2 C15.2 C16.2 C17.1 C18.2 C19.1 C20.1 C21.1 C22.2 C23.1 C24.1 C25.2 C26.2 C27.2 C28.2 C29.2 C30.2 C31.2 C32.2 C33.2 C34.1 C35.1 C36.1 CN1.A1(GND1) CN1.A12(GND2) CN1.B1(GND3) CN1.B12(GND4) CN1.SH1(Shield1) CN1.SH2(Shield2) CN1.SH3(Shield3) CN1.SH4(Shield4) CN17.3 JP3.2(NO) LD4.3(RED_cathode) LD6.3(RED_cathode) R5.2 R8.2 R14.2 R21.1 R24.2 R25.1 R30.2 R33.1 R34.2 R39.2 R41.1 U2.D5(VSS) U2.D6(BOOT0) U2.D7(VSS) U2.D8(VSS) U2.D9(VSS) U2.F2(VSS) U2.F6(VSS) U2.F7(VSS) U2.F8(VSS) U2.F9(VSS) U2.F10(VSS) U2.F12(VSS) U2.G2(VSS) U2.G6(VSS) U2.G7(VSS) U2.G8(VSS) U2.G9(VSS) U2.G10(VSS) U2.G12(VSS) U2.H6(VSS) U2.H7(VSS) U2.H8(VSS) U2.H9(VSS) U2.H10(VSS) U2.H12(VSS) U2.J6(VSS) U2.J7(VSS) U2.J8(VSS) U2.J9(VSS) U2.J10(VSS) U2.K6(VSS) U2.K7(VSS) U2.K8(VSS) U2.K9(VSS) U2.K10(VSS) U2.L4(BYPASS-REG) U2.M1(VSSA) U2.M8(VSS) U2.M9(VSS) U2.N1(VREF-) U3.3(GND) U3.4(GND) U4.2(GND) U7.2(GND) U7.9(EP) U8.8(GND) U8.9(EP) U11.2(GND) X1.2 X1.4
VBUS_STLK: C11.1 C17.2 C20.2 C21.2 CN1.A4(VBUS1) CN1.A9(VBUS2) CN1.B4(VBUS3) CN1.B9(VBUS4) D1.1(A) TP22.1 U4.1(IO1) U7.1(IN) U8.3(IN) U8.4(IN)
DBGIN.JTDI: R44.2 ; port DBGIN.JTDI
DBGIN.MCO: C3.2 R7.2 TP2.1 ; port DBGIN.MCO
DBGIN.SWCLK: R15.2 ; port DBGIN.SWCLK
DBGIN.SWDIO: R45.2 ; port DBGIN.SWDIO
DBGIN.SWO: R22.2 ; port DBGIN.SWO
DBGIN.VCP_RX: R20.2 TP17.1 ; port DBGIN.VCP_RX
DBGIN.VCP_TX: R16.2 TP15.1 ; port DBGIN.VCP_TX
NRST: R27.2 TP25.1 ; port NRST
STLK_LED: R11.1 R12.2 TP10.1 U2.D15(STLK_LED/PA10)
STLK_NRST: C1.2 JP3.1(COMMON) TP8.1 U2.J1(NRST)
STLK_OSC_IN: C35.2 U2.G1(OSC_IN/PH0) X1.1
STLK_OSC_OUT: C33.1 U2.H1(OSC_OUT/PH1) X1.3
STLK_SWCLK: CN17.2 U2.A14(STLK_SWCLK/PA14)
STLK_SWDIO: CN17.4 U2.A15(STLK_SWDIO/PA13)
STLK_UCPD_CC1_C: C10.1 R13.1 U2.M5(ADCx_IN13/PC3)
STLK_UCPD_CC2_C: C2.1 R6.1 U2.N5(ADCx_IN14/PC4)
STLK_USB_CN_N: CN1.A7(D-1) CN1.B7(D-2) U3.2(D-_con)
STLK_USB_CN_P: CN1.A6(D+1) CN1.B6(D+2) U3.1(D+_con)
STLK_USB_N: U2.R14(USB_DEV_HS_N/PB14) U3.5(D-_ic)
STLK_USB_P: U2.R15(USB_DEV_HS_P/PB15) U3.6(D+_ic)
STLK_VCP_RX: R16.1 TP12.1 U2.C10(STLK_VCP_RX/PG9)
STLK_VCP_TX: R20.1 TP16.1 U2.A7(STLK_VCP_TX/PG14)
T_JTDI: R44.1 U2.L3(T_JTDI/PF8)
T_PWR_EN: R21.2 R25.2 TP21.1 U2.R5(T_PWR_EN/PB0) U7.5(EN) U8.2(EN/UVLO)
T_PWR_EXT: R23.1 R24.1 TP24.1 U2.R4(T_PWR_EXT/PB1)
T_PWR_INT: C28.1 R33.2 R40.2 R41.2 R42.2 TP30.1 U2.J2(T_PWR_INT/ADC3_IN9/PF3)
T_PWR_LED: R9.2 R10.2 TP11.1 U2.H15(T_PWR_LED/PC6)
T_PWR_SEL1: R35.2 R37.2 TP32.1 U2.D10(T_PWR_SEL1/PD4)
T_PWR_SEL2: R36.2 R38.2 TP33.1 U2.C11(T_PWR_SEL2/PD5)
T_SWCLK: R15.1 U2.A10(T_JRCLK/PB3) U2.M6(T_JCLK_OUT/PB2) U2.M11(T_SWCLK/PH6)
T_SWDIO: R45.1 U2.L2(T_JTMS/T_SWDIO_OUT/PF9) U2.N12(T_SWDIO_IN/PH7)
T_SWO: R22.1 U2.A6(T_JTDO/PB5) U2.D12(T_SWO/PD2)
T_VCC: LNK1.2 R31.2
T_VCC_AIN: R30.1 R31.1 TP29.1 U2.N3(T_VCC_AIN/PA0)
NetC4_2: C4.2 TP9.1 U2.F13(VCAP2)
NetC7_2: C7.2 TP4.1 U2.J14(V12_OTGPHY)
NetC12_2: C12.2 TP13.1 U2.M10(VCAP1)
NetC19_2: C19.2 TP23.1 U8.1(dVdt)
NetC34_2: C34.2 D1.2(K) D2.2(K) TP36.1 U11.3(VIN) U11.5(EN)
NetCN1_A5: CN1.A5(CC1) R13.2 R14.1
NetCN1_B5: CN1.B5(CC2) R5.1 R6.2
NetLD4_1: LD4.1(Red_anode) R12.1 TP7.1
NetLD4_2: LD4.2(Green_cathode) R11.2 TP6.1
NetLD6_1: LD6.1(Red_anode) R10.1 TP1.1
NetLD6_2: LD6.2(Green_cathode) R9.1 TP5.1
NetR7_1: R7.1 U2.F15(T_MCO/PA8)
NetR8_1: R8.1 TP3.1 U2.J15(REXT_OTGPHY)
NetR27_1: R27.1 TP27.1 U2.P3(T_NRST/PA6)
NetR28_1: R28.1 TP34.1 U2.C4(HW_TYP_1/PI5)
NetR32_1: R32.1 TP31.1 U2.D4(HW_TYP_0/PI4)
NetR34_1: R34.1 R35.1 R36.1 TP28.1 U8.7(ILM)
NetR37_1: R37.1 R38.1 R39.1 U7.7(ILIM)

Not connected (* = marked no-connect by the designer): CN1 A2(TX1+)* A3(TX1-)* A8(SBU1)* A10(RX2-)* A11(RX2+)* B2(TX2+)* B3(TX2-)* B8(SBU2)* B10(RX1-)* B11(RX1+)*; U2 A2(GPIO0/PE2)* A5(I2C_SCL/PB8)* A9(SPI_NSS/PB4)* B1(GPIO1/PE4)* B2(GPIO2/PE5)* B3(GPIO3/PE6)* B4(I2C_SDA/PB9)* B14(UART_TX/PC10)* B15(CAN_TX/PA12)* C15(CAN_RX/PA11)* E15(SPI_SCK/PA9)* K13(GNDDetect/PG5)* M3(SPI_MOSI/PC1)* M4(SPI_MISO/PC2)* N6(T_JNRST/PF13)* N13(UART_RTS/PD12)* N14(UART_CTS/PD11)* R3(T_SW_DIR/PA7)* R13(UART_RX/PB11)*; U7 3(NC)* 4(NC)* 6(NC)*; U11 4(NC/ADJ)*

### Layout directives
differential pair; differential pair class DiffPair_90; net class 90 ohms diff: STLK_USB_CN_N, STLK_USB_CN_P, STLK_USB_N, STLK_USB_P

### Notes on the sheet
- USB STLINK
- (near TP2) MCO
- STLINK
- TARGET MCU
- All MCU.xxx signals are HiZ after POR, and only initialized after a PC connection to STLink dedicated protocol (either JTAG, or SWD, or VCP).
- PA13
- PB3
- PA14
- PD8
- PA15
- (near U3) U15 may be mirrored to optimize USB layout
- PD9
- (near X1) Cyrstal caps may be tuned to optimized accuracy (depending on the layout)
- (near JP3) STLK RST
- Target external supply
- Target Vio reference
- source indicator
- (near CN17) Reserved
- Discrete pull-up/down resistors should be placed on target side depending on the application and the target internall pulls. Recommended values (to be checked by the Designer) :
  - pull-up on Target RX signal
  - no pulls on Target TX signal (as it is internally present in STLink MCU)
  - no pulls on JTAG signals (as they are internally present in the targeted MCU)
  - no pulls on nRST signal (as it is internally present in the targeted MCU)
- (near CN17) 1
- 5V_STLK OVERCURRENT PROTECTION MANAGEMENT
- (current limit: 550mA)
- (current limit: 1.66A)
- Power1.5.SNK
- PowerDefault.SNK
- T_PWR_SEL2/PD5
- Hi-Z
- T_PWR_SEL1/PD4
- 0
- (current limit: 3.2A)
- Power3.0.SNK
- Hi-Z = IO set in high impedance
- PWR_STATUS
- COM

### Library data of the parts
C1 C5 C6 C8 C9 C13-C16 C18 C22 C25-C27 C29-C32 = MCD-00006: Capacitor, MLCC, 100nF, 16V, X7R, +/-10%, 0402, T=0.5mm; Manufacturer_Part_Number: CC0402KRX7R7BB104; Manufacturer: YAGEO; Part_Preference: Recommended; Partial_Alternate_Internal_Part_Number: MCD-03299; Order_Code_RS: 9402047; Component_Country_Of_Origin: China; ShowFields: YES; ID: 2474
C2 C10 C19 C28 = MCD-02198: Capacitor, MLCC, 10nF, 50V, X7R, +/-10%, 0402, T=0.5mm; Part_Preference: Recommended; Manufacturer: YAGEO; Manufacturer_Part_Number: CC0402KRX7R9BB103; Order_Code_RS: 6169644; Component_Country_Of_Origin: China; ShowFields: YES; ID: 4298
C3 = MCD-00016: Capacitor, MLCC, 20pF, 50V, NPO, +/- 5%, 0402, T=0.5mm; Manufacturer_Part_Number: CC0402JRNPO9BN200; Manufacturer: YAGEO; Part_Preference: Recommended; Component_Country_Of_Origin: China; ShowFields: YES; ID: 2479
C4 C7 C12 = MCD-02606: Capacitor, MLCC, 2.2uF, 6.3V, X5R, +/-10%, 0402, T=0.5mm; Part_Preference: Recommended; Manufacturer: YAGEO; Manufacturer_Part_Number: CC0402KRX5R5BB225; Order_Code_RS: 1992205; ShowFields: YES; ID: 4712; Component_Country_Of_Origin: China°
C11 = MCD-00205: Capacitor, MLCC, 100pF, 50V, NPO, +/-5%, 0402, T=0.5mm; Part_Preference: Recommended; Manufacturer: YAGEO; Manufacturer_Part_Number: CC0402JRNPO9BN101; Component_Country_Of_Origin: China; ShowFields: YES; ID: 2658
C17 = MCD-00095: Capacitor, MLCC, 1uF, 25V, X5R, +/-10%, 0402, T=0.5mm; Part_Preference: Recommended; Manufacturer: MURATA; Manufacturer_Part_Number: GRM155R61E105KA12; Order_Code_RS: 2218855; Component_Country_Of_Origin: Japan°°; ShowFields: YES; ID: 2772
C20 C21 = MCD-01099: Capacitor, MLCC, 100nF, 50V, X7R, +/-10%, 0603, T=0.8mm; BMS_Part_Number: 9142278; Part_Preference: Recommended; Manufacturer: YAGEO; Manufacturer_Part_Number: CC0603KRX7R9BB104; Order_Code_RS: 669-8767; Component_Country_Of_Origin: China; ShowFields: YES; ID: 3397
C23 C24 C36 = MCD-00099: as C91 on sheet Ethernet
C33 C35 = MCD-01374: Capacitor, MLCC, 5.6pF, 50V, NPO, +/-0.1pF, 0402, T=0.5mm; Part_Preference: Recommended; Manufacturer: YAGEO; Manufacturer_Part_Number: CC0402BRNPO9BN5R6; Component_Country_Of_Origin: China; ShowFields: YES; ID: 3474
C34 = MCD-02372: Capacitor, MLCC, 2.2uF, 25V, X7R, +/-10%, 0805, T=1,25mm; Manufacturer_Part_Number: GRM21BR71E225KE11L; Manufacturer: MURATA; Part_Preference: Recommended; Component_Country_Of_Origin: Japan°; ShowFields: YES; ID: 4478
CN1 = MCD-03232: USB_TypeC, 24 pins, RA, SMD, T=2.96mm; Part_Type: Connector; Part_Preference: Recommended; Manufacturer: AMPHENOL ICC; Manufacturer_Part_Number: 12401826E412A; Component_Country_Of_Origin: China°; ShowFields: YES; ID: 5348
CN17 = MCD-00029: Header, 4x1, 2.54mm, VR, TH, T=5.84mm/2.54mm; Manufacturer_Part_Number: TSW-104-07-G-S; Manufacturer: SAMTEC; Part_Type: Connector; Part_Preference: Recommended; Order_Code_RS: 2667450; Component_Country_Of_Origin: China, Costa Rica, Malaysia, USA, Vietnam; ShowFields: YES; ID: 2487
D1 D2 = MCD-03011: Diode, Schottky, 0V54, 1A, 23V, SOD-323; Part_Preference: Recommended; Manufacturer: STMICROELECTRONICS; Order_Code_RS: 165-7545; ShowFields: YES; ID: 5127; Component_Country_Of_Origin: China
JP3 = MCD-00045: Header, 2x1, 2.54mm, VR, TH, T=5.84mm/2.54mm; Part_Preference: Recommended; Part_Type: Connector; Manufacturer: SAMTEC; Manufacturer_Part_Number: TSW-102-07-G-S; Full_Alternate_Internal_Part_Number: MCD-02390; Partial_Alternate_Internal_Part_Number: MCD-02957, MCD-03720; Order_Code_RS: 2505044; Component_Country_Of_Origin: China, Costa Rica, Malaysia, USA, Vietnam; ShowFields: YES; ID: 2545
LD4 = MCD-02631: LED Bicolor, Red/Green, 2V, 20mA, 4-PLCC; Part_Type: Display; Part_Preference: Recommended; Manufacturer: WURTH ELEKTRONIK; Manufacturer_Part_Number: 150141SV73110; Partial_Alternate_Internal_Part_Number: MCD-02402; Order_Code_RS: 184-6963; Component_Country_Of_Origin: China; ShowFields: YES; ID: 4737
LD6 = MCD-02631: LED Bicolor, Green/Red, 2V, 20mA, 4-PLCC; Part_Type: Display; Part_Preference: Recommended; Manufacturer: WURTH ELEKTRONIK; Manufacturer_Part_Number: 150141SV73110; Order_Code_RS: 184-6963; Component_Country_Of_Origin: China; ShowFields: YES; ID: 4737
LNK1 = MCD-02777: Track link on PCB 200um width for layout routing; Part_Type: Misc; Part_Preference: Recommended; ShowFields: YES; ID: 4889
R5 R14 R23 = MCD-00333: Resistor, 5K1, 0402, +/-1%, 1/16W; Part_Preference: Recommended; Manufacturer: YAGEO; Manufacturer_Part_Number: RC0402FR-075K1L; Component_Country_Of_Origin: China; ShowFields: YES; ID: 2944
R6 R13 R21 R25 = MCD-00059: Resistor, 100K, 0402, +/-1%, 1/16W; Manufacturer_Part_Number: RC0402FR-07100KL; Manufacturer: YAGEO; Part_Preference: Recommended; Partial_Alternate_Internal_Part_Number: MCD-03301; Order_Code_RS: 2421891; Component_Country_Of_Origin: China; ShowFields: YES; ID: 2533
R7 = MCD-00067: Resistor, 100R, 0402, +/- 1%, 1/16W; Part_Preference: Recommended; Manufacturer: YAGEO; Manufacturer_Part_Number: RC0402FR-07100RL; Order_Code_RS: 9239111; Component_Country_Of_Origin: China; ShowFields: YES; ID: 2527
R8 = MCD-00185: Resistor, 3K, 0402, +/-1%, 1/16W; Manufacturer_Part_Number: RC0402FR-073KL; Manufacturer: YAGEO; Part_Preference: Recommended; Component_Country_Of_Origin: China; ShowFields: YES; ID: 2682
R9 R11 = MCD-00062: Resistor, 330R, 0402, +/-1%, 1/16W; Part_Preference: Recommended; Manufacturer: YAGEO; Manufacturer_Part_Number: RC0402FR-07330RL; Order_Code_RS: 9239170; Component_Country_Of_Origin: China; ShowFields: YES; ID: 2529
R10 R12 = MCD-00061: Resistor, 1K, 0402, +/-1%,1/16W; Part_Preference: Recommended; Manufacturer: YAGEO; Manufacturer_Part_Number: RC0402FR-071KL; Order_Code_RS: 9239235; Component_Country_Of_Origin: China; ShowFields: YES; ID: 2532
R15 R20 R44 R45 = MCD-00455: Resistor, 33R, 0402, +/-1%, 1/16W; Part_Preference: Recommended; Manufacturer: YAGEO; Manufacturer_Part_Number: RC0402FR-0733RL; Component_Country_Of_Origin: China; ShowFields: YES; ID: 2821
R16 R22 R27 = MCD-00052: Resistor, 0R, 0402, +/-5%, 1/16W; Part_Preference: Recommended; Manufacturer: YAGEO; Manufacturer_Part_Number: RC0402JR-070RL; Order_Code_RS: 9232516RL; Component_Country_Of_Origin: China; ShowFields: YES; ID: 2540
R24 R28 R30-R32 = MCD-00053: as R70 on sheet Ethernet
R33 R34 R41 = MCD-02455: Resistor, 3K9, 0402, +/-1%, 1/16W, +/-100ppm/°C; Part_Preference: Recommended; Manufacturer: YAGEO; Manufacturer_Part_Number: RC0402FR-073K9L; Order_Code_RS: 198-7783; Component_Country_Of_Origin: China; ShowFields: YES; ID: 4561
R35 = MCD-00409: Resistor, 1K8, 0402, +/-1%, 1/16W; Part_Preference: Recommended; Manufacturer: YAGEO; Manufacturer_Part_Number: RC0402FR-071K8L; Component_Country_Of_Origin: China; ShowFields: YES; ID: 2871
R36 = MCD-00381: Resistor, 1K3, 0402, +/-1%, 1/16W; Part_Preference: Recommended; Manufacturer: YAGEO; Manufacturer_Part_Number: RC0402FR-071K3L; Component_Country_Of_Origin: China; ShowFields: YES; ID: 2898
R37 = MCD-00513: Resistor, 680K, 0402, +/-1%, 1/16W; Part_Preference: Recommended; Manufacturer: YAGEO; Manufacturer_Part_Number: RC0402FR-07680KL; Component_Country_Of_Origin: China; ShowFields: YES; ID: 3227
R38 = MCD-00483: Resistor, 470K, 0402, +/-1%, 1/16W; Part_Preference: Recommended; Manufacturer: YAGEO; Manufacturer_Part_Number: RC0402FR-07470KL; Component_Country_Of_Origin: China; ShowFields: YES; ID: 2797
R39 = MCD-00387: Resistor, 1M3, 0402, +/-1%, 1/16W; Part_Preference: Recommended; Manufacturer: YAGEO; Manufacturer_Part_Number: RC0402FR-071M3L; Component_Country_Of_Origin: China; ShowFields: YES; ID: 2893
R40 R42 = MCD-00185: Resistor, 3K, 0402, +/-1%, 1/16W; Part_Preference: Recommended; Manufacturer: YAGEO; Manufacturer_Part_Number: RC0402FR-073KL; Component_Country_Of_Origin: China; ShowFields: YES; ID: 2682
TP1 TP3-TP13 TP15-TP17 TP21-TP36 = MCD-00631: as TP54 on sheet Ethernet
TP2 = MCD-00074: Test Point 1mm; Part_Type: Misc; Part_Preference: Recommended; ShowFields: YES; ID: 2518
U2 = MCD-03851: MCU, ARM Cortex-M7 32-bit, 512KB Flash, 276KB RAM, With Crypto; Part_Type: IC; Part_Preference: Recommended; Manufacturer: STMICROELECTRONICS; Manufacturer_Part_Number: STM32F723IEK6; ShowFields: YES; ID: 5967
U3 = MCD-03060: IC, ESD protection and Common Filter High Speed serial Interfaces, 10.7 GHz; Part_Preference: Recommended; Manufacturer: STMICROELECTRONICS; Component_Country_Of_Origin: China; ShowFields: YES; ID: 5176
U4 = MCD-01207: Diode, ESD TVS, 22V, 200nA, 25V8, QFN1610; Manufacturer: STMICROELECTRONICS; BMS_Part_Number: 9179045; Part_Preference: Recommended; Manufacturer_HQ_COO: EU; Component_Country_Of_Origin: China; ShowFields: YES; ID: 3289; Order_Code_RS: 163-9774
U7 = MCD-03814: IC, eFuse with Overvoltage Protection 2V7 to 28V , 6V2 voltage clamp, 5A adjustable, 50mR; Part_Preference: Not recommended; Manufacturer: LITTELFUSE; Component_Country_Of_Origin: China°; ShowFields: YES; ID: 5930
U8 = MCD-02532: IC, 2V7 to 18V, 4A, 34mR, eFuse with fast overvoltage protection; Part_Preference: Recommended; Manufacturer: TEXAS INSTRUMENTS; ShowFields: YES; ID: 4638
U11 = MCD-02514: LDO, 300mA, 28V, Low-dropout voltage, with 5uA quiescent current; Part_Type: IC; Part_Preference: Recommended; Manufacturer: STMICROELECTRONICS; Component_Country_Of_Origin: Malaysia; ShowFields: YES; ID: 4620
X1 = MCD-01036: Crystal, 24MHz, 6pF, +/-20ppm, 80R, 2x1.6mm; BMS_Part_Number: 9157045; Part_Type: Crystal_Osc; Part_Preference: Recommended; Manufacturer: NDK; Manufacturer_Part_Number: NX2016SA-24MHZ-EXS00A-CS10820; Component_Country_Of_Origin: Unknown; ShowFields: YES; ID: 2989

## Sheet External_Debug_Interface.SchDoc: External Debug Interface
size A4; Date: Not used; ApprovedBy: Not used; CheckedBy: Not used; Author: Not used; CompanyName: STMicroelectronics; DrawnBy: Not used; Engineer: Not used; Organization: Not used; Address1: Not used; Address2: Not used; Address3: Not used; Address4: Not used; DocumentNumber: 13; Revision: Not used; SheetNumber: 13; SheetTotal: 14
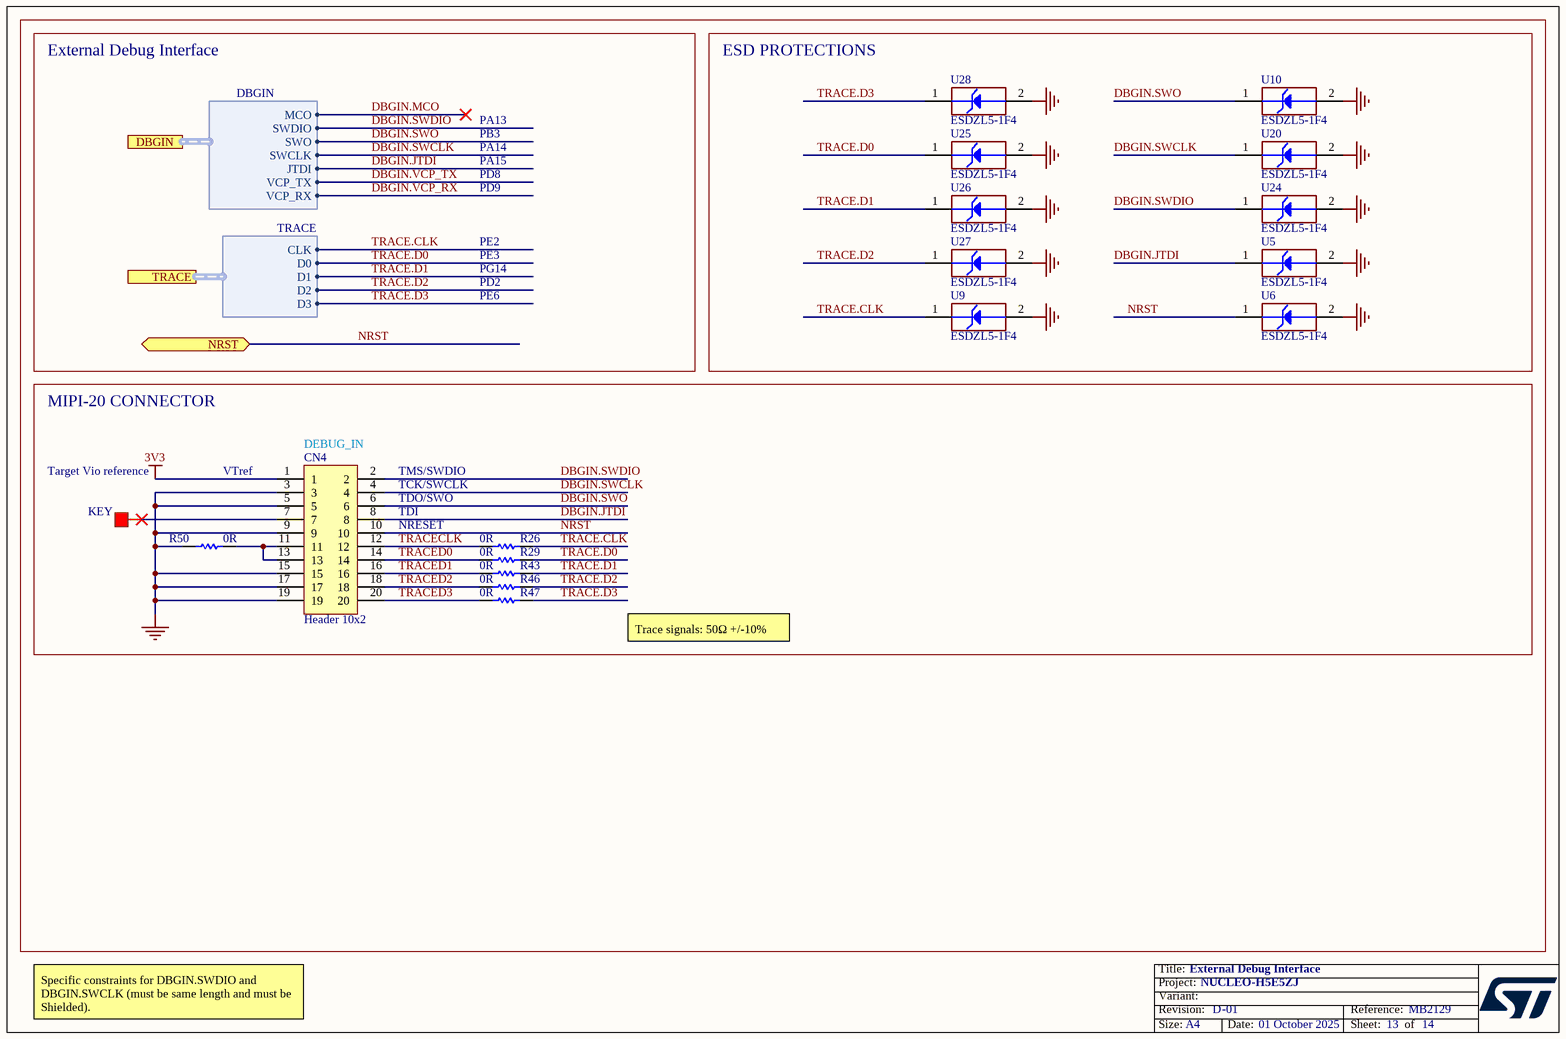
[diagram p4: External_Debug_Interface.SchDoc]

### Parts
CN4  Header 10x2  [CON_SAMTEC_FTSH-110-01-L-DV]
R26  value 0R  [R0402]  (hidden comment: Resistor)
R29  value 0R  [R0402]  (hidden comment: Resistor)
R43  value 0R  [R0402]  (hidden comment: Resistor)
R46  value 0R  [R0402]  (hidden comment: Resistor)
R47  value 0R  [R0402]  (hidden comment: Resistor)
R50  value 0R  [R0402]  (hidden comment: Resistor)
U5  value ESDZL5-1F4  [ESD_0201_H0P3_1K_2A]  (hidden comment: ESD-TRANSIL)
U6  value ESDZL5-1F4  [ESD_0201_H0P3_1K_2A]  (hidden comment: ESD-TRANSIL)
U9  value ESDZL5-1F4  [ESD_0201_H0P3_1K_2A]  (hidden comment: ESD-TRANSIL)
U10  value ESDZL5-1F4  [ESD_0201_H0P3_1K_2A]  (hidden comment: ESD-TRANSIL)
U20  value ESDZL5-1F4  [ESD_0201_H0P3_1K_2A]  (hidden comment: ESD-TRANSIL)
U24  value ESDZL5-1F4  [ESD_0201_H0P3_1K_2A]  (hidden comment: ESD-TRANSIL)
U25  value ESDZL5-1F4  [ESD_0201_H0P3_1K_2A]  (hidden comment: ESD-TRANSIL)
U26  value ESDZL5-1F4  [ESD_0201_H0P3_1K_2A]  (hidden comment: ESD-TRANSIL)
U27  value ESDZL5-1F4  [ESD_0201_H0P3_1K_2A]  (hidden comment: ESD-TRANSIL)
U28  value ESDZL5-1F4  [ESD_0201_H0P3_1K_2A]  (hidden comment: ESD-TRANSIL)

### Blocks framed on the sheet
ESD PROTECTIONS: U5 U6 U9 U10 U20 U24-U28
MIPI-20 CONNECTOR: CN4 R26 R29 R43 R46 R47 R50

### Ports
DBGIN (harness DBGIN), NRST (bidir), TRACE (harness TRACE)

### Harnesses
TRACE: CLK, D0, D1, D2, D3
DBGIN: SWDIO, SWO, VCP_TX, SWCLK, VCP_RX, MCO, JTDI

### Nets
3V3: CN4.1
GND: CN4.3 CN4.5 CN4.9 CN4.15 CN4.17 CN4.19 R50.1 U5.2(GND) U6.2(GND) U9.2(GND) U10.2(GND) U20.2(GND) U24.2(GND) U25.2(GND) U26.2(GND) U27.2(GND) U28.2(GND)
DBGIN.JTDI: CN4.8 U5.1(IO1) ; port DBGIN.JTDI
DBGIN.SWCLK: CN4.4 U20.1(IO1) ; port DBGIN.SWCLK
DBGIN.SWDIO: CN4.2 U24.1(IO1) ; port DBGIN.SWDIO
DBGIN.SWO: CN4.6 U10.1(IO1) ; port DBGIN.SWO
NRST: CN4.10 U6.1(IO1) ; port NRST
TRACE.CLK: R26.2 U9.1(IO1) ; port TRACE.CLK
TRACE.D0: R29.2 U25.1(IO1) ; port TRACE.D0
TRACE.D1: R43.2 U26.1(IO1) ; port TRACE.D1
TRACE.D2: R46.2 U27.1(IO1) ; port TRACE.D2
TRACE.D3: R47.2 U28.1(IO1) ; port TRACE.D3
TRACECLK: CN4.12 R26.1
TRACED0: CN4.14 R29.1
TRACED1: CN4.16 R43.1
TRACED2: CN4.18 R46.1
TRACED3: CN4.20 R47.1
NetCN4_11: CN4.11 CN4.13 R50.2

Not connected (* = marked no-connect by the designer): CN4 7*

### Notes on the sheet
- PA13
- PB3
- PA14
- PA15
- PD8
- PE2
- PD9
- PE3
- PG14
- PD2
- PE6
- (near CN4) DEBUG_IN
- Target Vio reference
- KEY
- VTref
- (near CN4) TMS/SWDIO
- (near CN4) TCK/SWCLK
- (near CN4) TDO/SWO
- (near CN4) TDI
- NRESET
- Trace signals: 50Ω +/-10%
- Specific constraints for DBGIN.SWDIO and DBGIN.SWCLK (must be same length and must be Shielded).

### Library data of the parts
CN4 = MCD-00557: Header, 10x2, 1.27mm, VR, SMD, T=3.05mm; BMS_Part_Number: 9183690; Part_Type: Connector; Part_Preference: Recommended; Manufacturer: SAMTEC; Manufacturer_Part_Number: FTSH-110-01-L-DV; Order_Code_RS: 767-6774; Component_Country_Of_Origin: China, Costa Rica, Malaysia, United States, Vietnam; ShowFields: YES; ID: 3188
R26 R29 R43 R46 R47 = MCD-00052: as R79 on sheet Ethernet
R50 = MCD-00052: as R16 on sheet STLINK_V3EC
U5 U6 U9 U10 U20 U24-U28 = MCD-03501: Diode, ESD TVS, 5V5, 100nA, 10V, 0201; Part_Preference: Recommended; Manufacturer: STMICROELECTRONICS; Component_Country_Of_Origin: Singapore; ShowFields: YES; ID: 5617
